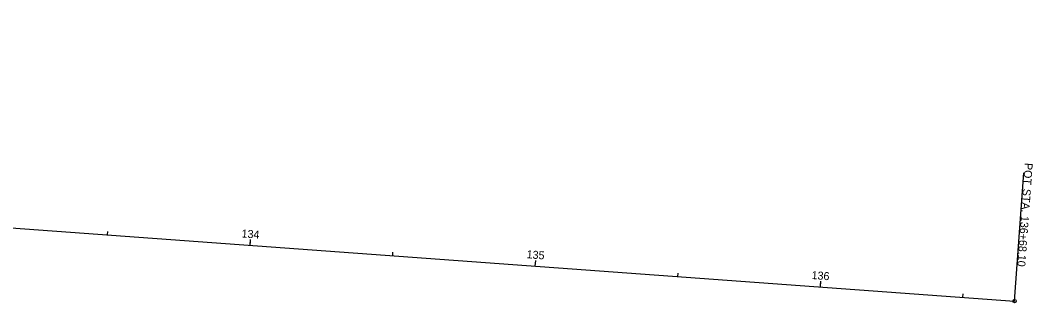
# Model space of a CAD drawing. Extents: x 1898401 to 1901169, y 703131 to 703379.
# Drawn here: x 1900814.4 to 1901168.5, y 703130.8 to 703229.8 of the extents above; entities that cross this region are included whole.
import ezdxf

# ---------------------------------------------------------------- set-up
doc = ezdxf.new("R2010")
doc.units = 0
for name, color, linetype in [('RW_X_CL', 7, 'Continuous'), ('RW_X_CL_1000_Cardinal_Points', 7, 'Continuous'), ('RW_X_CL_1000_Stations', 7, 'Continuous'), ('RW_X_CL_100_Cardinal_Points', 7, 'Continuous'), ('RW_X_CL_100_Stations', 7, 'Continuous'), ('RW_X_CL_500_Cardinal_Points', 7, 'Continuous'), ('RW_X_CL_500_Stations', 7, 'Continuous')]:
    doc.layers.add(name, color=color, linetype=linetype)

msp = doc.modelspace()

# ---------------------------------------------------------------- linework, layer by layer
at = {"layer": 'RW_X_CL'}
msp.add_line((1899815.76, 703229.84), (1901162.17, 703131.42), dxfattribs=at)
at = {"layer": 'RW_X_CL_1000_Cardinal_Points'}
msp.add_line((1901162.17, 703131.42), (1901165.45, 703176.3), dxfattribs=at)
msp.add_circle((1901162.17, 703131.42), 0.6, dxfattribs=at)
at = {"layer": 'RW_X_CL_1000_Stations'}
msp.add_line((1900994.52, 703143.67), (1900994.6, 703144.87), dxfattribs=at)
at = {"layer": 'RW_X_CL_100_Cardinal_Points'}
msp.add_line((1901162.17, 703131.42), (1901165.45, 703176.3), dxfattribs=at)
msp.add_circle((1901162.17, 703131.42), 0.6, dxfattribs=at)
at = {"layer": 'RW_X_CL_100_Stations'}
for p, q in [((1900844.91, 703154.61), (1900845, 703155.81)), ((1900894.78, 703150.96), (1900894.93, 703152.96)), ((1900944.65, 703147.32), (1900944.74, 703148.52)), ((1900994.52, 703143.67), (1900994.66, 703145.67)), ((1901044.38, 703140.03), (1901044.47, 703141.23)), ((1901094.25, 703136.38), (1901094.4, 703138.38)), ((1901144.12, 703132.74), (1901144.2, 703133.93))]:
    msp.add_line(p, q, dxfattribs=at)
at = {"layer": 'RW_X_CL_500_Cardinal_Points'}
msp.add_line((1901162.17, 703131.42), (1901165.45, 703176.3), dxfattribs=at)
msp.add_circle((1901162.17, 703131.42), 0.6, dxfattribs=at)
at = {"layer": 'RW_X_CL_500_Stations'}
for p, q in [((1900894.78, 703150.96), (1900894.87, 703152.16)), ((1900994.52, 703143.67), (1900994.66, 703145.67)), ((1901094.25, 703136.38), (1901094.34, 703137.58))]:
    msp.add_line(p, q, dxfattribs=at)

# ---------------------------------------------------------------- texts
at = {"layer": 'RW_X_CL_1000_Cardinal_Points'}
for s, p in [('POT', (1901165.76, 703179.91)), (' STA. ', (1901165.18, 703171.89)), ('136+68.10', (1901164.41, 703161.34))]:
    msp.add_text(s, height=2.8, rotation=265.8192, dxfattribs=at).set_placement(p)
at = {"layer": 'RW_X_CL_100_Cardinal_Points'}
for s, p in [('POT', (1901165.76, 703179.91)), (' STA. ', (1901165.18, 703171.89)), ('136+68.10', (1901164.41, 703161.34))]:
    msp.add_text(s, height=2.8, rotation=265.8192, dxfattribs=at).set_placement(p)
at = {"layer": 'RW_X_CL_100_Stations'}
for s, p in [('134', (1900891.7, 703153.74)), ('135', (1900991.41, 703146.45)), ('136', (1901091.09, 703139.16))]:
    msp.add_text(s, height=2.8, rotation=355.8192, dxfattribs=at).set_placement(p)
at = {"layer": 'RW_X_CL_500_Cardinal_Points'}
for s, p in [('POT', (1901165.76, 703179.91)), (' STA. ', (1901165.18, 703171.89)), ('136+68.10', (1901164.41, 703161.34))]:
    msp.add_text(s, height=2.8, rotation=265.8192, dxfattribs=at).set_placement(p)
at = {"layer": 'RW_X_CL_500_Stations'}
msp.add_text('135', height=2.8, rotation=355.8192, dxfattribs=at).set_placement((1900991.41, 703146.45))

doc.saveas('drawing.dxf')
